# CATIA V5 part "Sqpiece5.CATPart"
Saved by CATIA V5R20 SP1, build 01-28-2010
Part number: Sqpiece5
Publications: "Plan.2", "Droite.1", "Droite.2", "Plan.1", "Longueur5"
Bounding box of the stored display mesh (mm): x 0 to 130, y -20 to 20, z 0 to 0
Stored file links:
  C:\Users\RENARD Simon\Documents\Cours IFMA\2ème année\IAO\Sqpiece5.CATPart
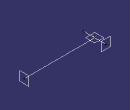
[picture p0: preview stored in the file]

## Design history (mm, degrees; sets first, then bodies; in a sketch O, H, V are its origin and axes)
Parameters
  Longueur5 = 130 mm
Body1 (main body)
  Point1: (0, 0, 0)
  Line1: type PtDir, RefPoint Point1, Direction yz-plane, Start 0, End 130 {= Longueur5}
  Plane1: type OffsetPt, RefPlane yz-plane, RefPoint vertex of Line1
  Line2: type PtDir, RefPoint Point1, Direction zx-plane, Start -20, End 20
  Plane2: type OffsetPt, RefPlane zx-plane, RefPoint vertex of Line2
